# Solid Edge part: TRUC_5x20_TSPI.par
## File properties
Title: 1320006490
Subject: Vite truciolare 5x20 TSPIC
Author: g_deluca
Template: Acciaio.par
Last saved by: b_giovanelli
Revision: 28
Application: Solid Edge
Tipo di contenuto documento: 0
Material: C15
Stile della faccia: Acciaio
Stile di riempimento: ANSI32(Acciaio)
Stile virtuale: Acciaio lavorato a macchina
Coef. of Thermal Exp: 0.0
Thermal Conductivity: 32.0
Specific Heat: 481.0
Modulus of Elasticity: 199947953000.0
Poission's Ratio: 0.29
Yield Stress: 262000766.0
Ultimate Stress: 358527364.0
Elongation: 0.0
Company: EFFEBI S.p.A.
custom2: 2001-08-01
DIMENSIONI: .
Densità: 7833.000 kg/m^3
Precisione: 0.99
Revision: /
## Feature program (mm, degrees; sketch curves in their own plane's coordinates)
sketch for "unnamed RevolvedProtrusion 1" plane through (0, 0, 0) normal (0, -1, 0) x-axis (1, 0, 0)
revolve "unnamed RevolvedProtrusion 1" add full turn 360 deg about sketch line (0, 0) -> (0, -20)
sketch for "unnamed Cutout 1" plane through (0, 0, 0) normal (0, 0, 1) x-axis (0, 1, 0)
  line (-2.5, 0.6) -> (-2.5, -0.6)
  line (-2.5, -0.6) -> (-0.6, -0.6)
  line (-0.6, -0.6) -> (-0.6, -2.5)
  line (-0.6, -2.5) -> (0.6, -2.5)
  line (0.6, -2.5) -> (0.6, -0.6)
  line (0.6, -0.6) -> (2.5, -0.6)
  line (2.5, -0.6) -> (2.5, 0.6)
  line (2.5, 0.6) -> (0.6, 0.6)
  line (0.6, 0.6) -> (0.6, 2.5)
  line (0.6, 2.5) -> (-0.6, 2.5)
  line (-0.6, 2.5) -> (-0.6, 0.6)
  line (-0.6, 0.6) -> (-2.5, 0.6)
extrude "unnamed Cutout 1" cut finite 1.2 along -normal
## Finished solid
Body 1: solid body, 18 faces, 40 edges, 24 vertices.
  Faces by surface: plane 14, cone 2, cylinder 2
  Edges by curve: line 36, circle 4
Bounding box of the edges (mm): 9.600 x 9.600 x 14.206, from (-4.8, -4.8, -14.2059) to (4.8, 4.8, 0).
Cylindrical faces by radius (mm): R2.4 x1, R4.8 x1
Conical faces (half-angle, radius in mm at the cone's reference point): 22.5 deg R0 x1, 45 deg R2.4 x1
Planar faces by outward normal: +x 3, +y 3, +z 2, -x 3, -y 3
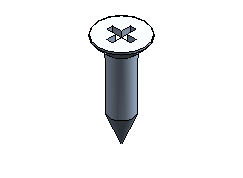
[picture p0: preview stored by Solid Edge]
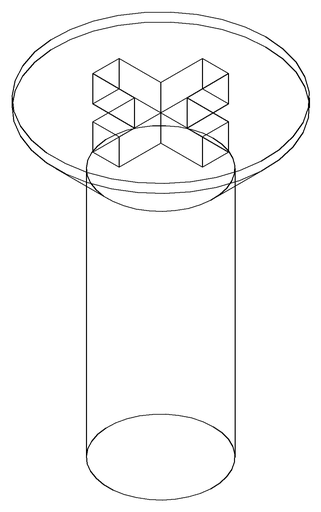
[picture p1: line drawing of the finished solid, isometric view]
